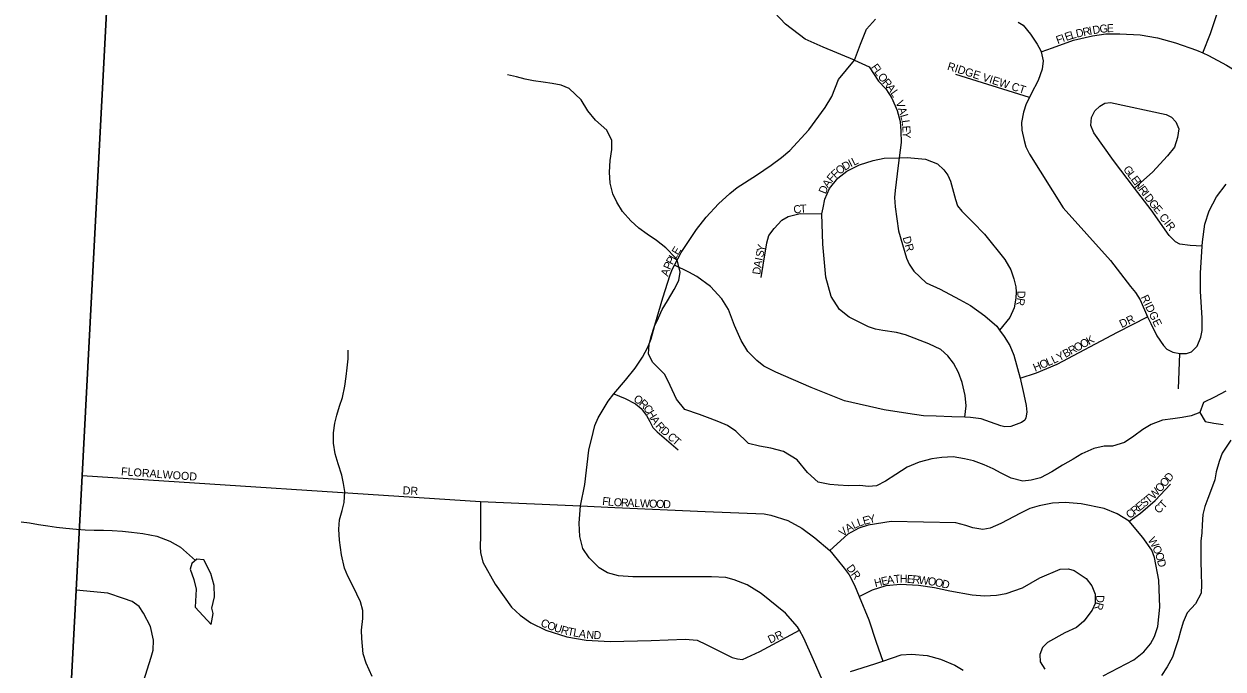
# Model space of a CAD drawing. Extents: x 1759416 to 2214760, y 252598 to 1116833.
# Drawn here: x 2005444 to 2012935, y 891835 to 895864 of the extents above; entities that cross this region are included whole.
import ezdxf

# ---------------------------------------------------------------- set-up
doc = ezdxf.new("R2010")
doc.units = 0
for name, color, linetype in [('GM_X_County_Road', 7, 'Continuous'), ('GM_X_County_Subdivision', 7, 'Continuous'), ('GM_X_County_Subdivision_Text', 7, 'Continuous'), ('GM_X_Major_Lake', 7, 'Continuous'), ('GM_X_Minor_Lake', 7, 'Continuous'), ('GM_X_Minor_River', 7, 'Continuous'), ('GM_X_Township', 7, 'Continuous'), ('GM_X_Township_Subdivision', 7, 'Continuous'), ('GM_X_Township_Subdivision_Text', 7, 'Continuous')]:
    doc.layers.add(name, color=color, linetype=linetype)

msp = doc.modelspace()

# ---------------------------------------------------------------- linework, layer by layer
at = {"layer": 'GM_X_County_Road'}
msp.add_lwpolyline([(2004887.1, 877838.9), (2004966.1, 878054.7), (2005006.3, 878210), (2005059.3, 878425.5), (2005076, 878622.8), (2005114.2, 879911.6), (2005203.2, 881311.9), (2005266.8, 882813.7), (2005306.3, 883397.6), (2005439.1, 886066.7), (2005449.8, 886268.9), (2005489.1, 887010.5), (2005555.5, 888282.1), (2005602.6, 889171.2), (2005650.9, 890084.8), (2005769.6, 892327), (2005807.5, 893043.9), (2005864.5, 894121.1), (2005998.4, 896652.4), (2006004, 896754.8), (2006008, 896849.4)], dxfattribs=at)
at = {"layer": 'GM_X_County_Subdivision'}
for points in [[(2010433.5, 891763), (2010377.4, 891893.1), (2010316.5, 892029), (2010288.5, 892077.4), (2010276.1, 892098.9), (2010201.5, 892184.6), (2010050.5, 892308), (2009962.1, 892361.6), (2009881.8, 892393.2), (2009829.7, 892406.9), (2009739.6, 892410.4), (2009247, 892411.5), (2009158.9, 892416.9), (2009088.7, 892436.6), (2009038.4, 892466.4), (2008976, 892530.1), (2008935.6, 892588), (2008917.1, 892662), (2008912.6, 892746.2), (2008921.9, 892854.4), (2008947.1, 892986.8), (2008973.8, 893201.4), (2008999.2, 893311.8), (2009010.9, 893355.9), (2009030.6, 893404.1), (2009094.1, 893508.7), (2009129.8, 893555), (2009201.4, 893639.6), (2009263, 893714.1), (2009308.6, 893782.5), (2009342.3, 893844.8), (2009362, 893897.1), (2009385.4, 893983.3), (2009434.5, 894154), (2009481.6, 894296.5), (2009495.4, 894334.7), (2009507.3, 894356.7), (2009550.8, 894437.2), (2009646.1, 894580), (2009705.7, 894658.5), (2009783.2, 894741.2), (2009854.9, 894805.7), (2009898.7, 894842), (2010020.4, 894918.9), (2010112.1, 894981.6), (2010175.9, 895030), (2010229.7, 895074.4), (2010347, 895203.4), (2010450.2, 895342.2), (2010491.9, 895410.6), (2010533.2, 895517.1), (2010633, 895637.9), (2010669.6, 895737.2), (2010708.5, 895832.2), (2010763.5, 895894.8)], [(2005807.5, 893043.9), (2008296.7, 892881.4), (2008921.9, 892854.4)]]:
    msp.add_lwpolyline(points, dxfattribs=at)
at = {"layer": 'GM_X_Major_Lake'}
for points in [[(2012952.8, 893571), (2012880.9, 893532.6), (2012812.9, 893500.3), (2012789.1, 893438.1), (2012823.4, 893382.1)], [(2012823.4, 893382.1), (2012877.5, 893370.3), (2012935.6, 893362.5)], [(2012984.1, 893264.4), (2012930.3, 893184.1), (2012910.5, 893131.9), (2012892.7, 893067.7), (2012882.9, 893017.6), (2012863, 892961.4), (2012839.2, 892901.2), (2012821.4, 892851), (2012809.6, 892800.8), (2012803.8, 892736.7), (2012802, 892686.6), (2012796.2, 892634.4), (2012796.7, 892508.2), (2012799, 892432), (2012801.2, 892361.9), (2012797.4, 892309.8), (2012763.6, 892243.5), (2012709.8, 892187.2), (2012686, 892129), (2012668.2, 892070.8), (2012654.4, 892016.7), (2012636.5, 891960.5), (2012618.7, 891910.3), (2012586.9, 891848.1), (2012551.1, 891795.8)]]:
    msp.add_lwpolyline(points, dxfattribs=at)
at = {"layer": 'GM_X_Minor_Lake'}
for points in [[(2006613.5, 892114.2), (2006627.2, 892182.4), (2006617.1, 892214.5), (2006634.9, 892286.7), (2006632.6, 892356.8), (2006612.3, 892432.9), (2006567.9, 892516.9), (2006523.8, 892520.8), (2006493.9, 892494.6), (2006482, 892458.5), (2006506.3, 892394.5), (2006520.5, 892334.4), (2006512.9, 892222.1)], [(2006512.9, 892222.1), (2006613.5, 892114.2)]]:
    msp.add_lwpolyline(points, dxfattribs=at)
at = {"layer": 'GM_X_Minor_River'}
for points in [[(2012789.2, 893437.9), (2012735.1, 893415.9), (2012679.1, 893405.7), (2012621, 893397.5), (2012557, 893389.2), (2012485, 893362.9), (2012433, 893330.7), (2012377.1, 893290.4), (2012319.2, 893250.1), (2012245.2, 893227.8), (2012193.1, 893227.7), (2012127.1, 893213.4), (2012053.1, 893179.1), (2011999.1, 893146.8), (2011931.2, 893108.5), (2011865.2, 893066.2), (2011795.3, 893029.9), (2011737.3, 893015.7), (2011683.2, 893009.4), (2011611, 893027.2), (2011548.8, 893059.1), (2011498.7, 893085), (2011442.5, 893110.9), (2011376.3, 893134.7), (2011320.2, 893148.5), (2011248, 893160.3), (2011177.9, 893156), (2011115.9, 893147.8), (2011035.8, 893127.5), (2010961.9, 893095.2), (2010889.9, 893050.8), (2010826, 893008.5), (2010770, 892980.3), (2010720, 892976.1), (2010665.9, 892981.9), (2010595.8, 892979.7), (2010529.7, 892983.5), (2010477.6, 892987.3), (2010405.4, 893003.1), (2010339.1, 893063), (2010274.7, 893142.9), (2010188.4, 893194.8), (2010110.2, 893214.5), (2010040.1, 893226.3), (2009969.9, 893244.1), (2009891.5, 893320), (2009839.3, 893355.9), (2009785.1, 893379.8), (2009731, 893399.6), (2009664.8, 893425.4), (2009572.5, 893457.2), (2009520.2, 893521.2), (2009481.8, 893605.2), (2009447.5, 893675.2), (2009371.1, 893751.1), (2009344.9, 893803.2), (2009350.7, 893861.3), (2009362.5, 893911.4), (2009384.3, 893977.7), (2009408.1, 894029.8), (2009431.9, 894080), (2009463.8, 894134.2), (2009505.6, 894206.5), (2009535.4, 894262.8), (2009543.2, 894314.9), (2009526.9, 894383), (2009514.8, 894403), (2009454.5, 894466.9), (2009396.2, 894510.8), (2009338, 894550.7), (2009285.8, 894588.6), (2009235.5, 894634.5), (2009183.3, 894692.5), (2009147, 894750.5), (2009122.7, 894802.5), (2009106.5, 894870.6), (2009102.2, 894938.7), (2009105.9, 895010.9), (2009115.7, 895081.1), (2009117.5, 895137.2), (2009085.2, 895201.2), (2009014.8, 895263.1), (2008966.5, 895321), (2008924.2, 895391), (2008849.8, 895460.9), (2008799.7, 895482.8), (2008743.6, 895492.6), (2008687.5, 895500.5), (2008627.4, 895508.3), (2008575.2, 895520.1), (2008521.1, 895534), (2008465, 895545.8)], [(2007620.1, 891789), (2007581.8, 891871.1), (2007563.5, 891931.1), (2007555.1, 892025.3), (2007553, 892077.4), (2007560.7, 892151.6), (2007560.5, 892201.7), (2007546.3, 892255.7), (2007501.8, 892349.8), (2007467.5, 892415.8), (2007447.3, 892465.8), (2007427, 892547.9), (2007414.6, 892640.1), (2007410.3, 892708.2), (2007416.1, 892766.4), (2007431.9, 892824.5), (2007443.8, 892874.7), (2007449.5, 892944.9), (2007441.3, 892994.9), (2007429.1, 893047), (2007406.8, 893117.1), (2007388.5, 893179.2), (2007378.2, 893245.2), (2007378, 893311.4), (2007385.8, 893371.5), (2007399.6, 893421.7), (2007415.4, 893477.9), (2007433.2, 893532), (2007449, 893602.2), (2007456.8, 893662.4), (2007462.6, 893716.5), (2007470.4, 893772.7), (2007470.1, 893826.8)], [(2005427.4, 892755.5), (2005479.5, 892747.7), (2005535.6, 892737.9), (2005593.7, 892730), (2005647.8, 892722.2), (2005705.9, 892714.4), (2005772, 892708.6), (2005826.1, 892704.8), (2005882.2, 892703), (2005940.3, 892703.2), (2005994.4, 892701.4), (2006060.5, 892695.6), (2006116.6, 892689.8), (2006186.7, 892682), (2006274.9, 892664.2), (2006355.1, 892634.5), (2006421.4, 892596.6), (2006516.2, 892514.1)]]:
    msp.add_lwpolyline(points, dxfattribs=at)
at = {"layer": 'GM_X_Township'}
for points in [[(1998107.8, 897126.5), (1999328.7, 897063.4), (2003204.9, 896913.2), (2006004, 896754.8), (2005998.4, 896652.4), (2005864.5, 894121.1), (2005807.5, 893043.9), (2005769.6, 892327), (2005650.9, 890084.8), (2005602.6, 889171.2), (2005555.5, 888282.1), (2005489.1, 887010.5), (2005449.8, 886268.9), (2005439.1, 886066.7), (2005306.3, 883397.6)], [(2005306.3, 883397.6), (2005439.1, 886066.7), (2005449.8, 886268.9), (2005489.1, 887010.5), (2005555.5, 888282.1), (2005602.6, 889171.2), (2005650.9, 890084.8), (2005769.6, 892327), (2005807.5, 893043.9), (2005864.5, 894121.1), (2005998.4, 896652.4), (2010326.5, 896491.5), (2011122.5, 896461.9), (2011648.1, 896428), (2012134.2, 896416.9), (2013353.6, 896345), (2014249.7, 896310.5), (2015226.5, 896288.6), (2016682.3, 896255.5), (2022025.3, 896071.6)]]:
    msp.add_lwpolyline(points, dxfattribs=at)
at = {"layer": 'GM_X_Township_Subdivision'}
for points in [[(2010633, 895637.9), (2010436.5, 895719.9), (2010324.3, 895769.6), (2010201.2, 895862.4), (2010132.2, 895935.8), (2010106.2, 895980), (2010077.1, 896045.8), (2010060.9, 896112.8), (2010072.8, 896195.9), (2010113.8, 896269.3), (2010166.7, 896338.3), (2010254.1, 896423.6), (2010326.5, 896491.4), (2010327.6, 896492.2)], [(2012808.9, 895683), (2012857, 895804), (2012910.4, 895967.9), (2012927, 896039.9), (2012925.4, 896084), (2012911.8, 896132.2), (2012892, 896158.4), (2012864.2, 896182.7), (2012808.3, 896211.2), (2012358, 896362.9), (2012202.7, 896393.3), (2012064.3, 896398.1), (2011937.6, 896386.4), (2011858, 896369.6), (2011775.6, 896366.1), (2011716.3, 896383.7), (2011698.1, 896395.6)], [(2011654.5, 895876.2), (2011686.4, 895855.9), (2011732, 895801.4), (2011773.5, 895737), (2011795.2, 895700.7), (2011797.9, 895690.3), (2011803, 895670.6), (2011810.7, 895634.5), (2011804.2, 895582.4), (2011779.6, 895510.5), (2011736.9, 895428.7), (2011725.1, 895405.6), (2011704.4, 895364.8), (2011687.9, 895312.9), (2011675.4, 895248.9), (2011677, 895200.8), (2011692.5, 895136.5), (2011702.2, 895096.4), (2011725.8, 895050.1), (2011935.2, 894715.7), (2012232.8, 894386.6), (2012357.6, 894225.3), (2012387.3, 894187), (2012417, 894140.6), (2012462.1, 894034), (2012483.8, 893993.8), (2012521.2, 893917.3), (2012562.8, 893856.9), (2012584.6, 893832.6), (2012620.5, 893814.3), (2012664.4, 893805.9), (2012706.5, 893805.6), (2012738.6, 893817.3), (2012772.9, 893851.1), (2012795.4, 893907), (2012803.7, 893949), (2012804.4, 894027.1), (2012793.8, 894195.6), (2012794.7, 894307.8), (2012804.6, 894475.7), (2012806.3, 894504), (2012821.2, 894614.1), (2012847.9, 894698), (2012894.7, 894783.8), (2012955.4, 894863.5)], [(2011797.9, 895690.3), (2011869.4, 895716.1), (2011999.9, 895763.1), (2012120.2, 895790.2), (2012202.4, 895803.5), (2012290.5, 895802.8), (2012416.6, 895795.7), (2012526.5, 895776.8), (2012638.4, 895745.7), (2012768.1, 895700.6), (2012808.9, 895683), (2012843.9, 895667.9), (2012955.5, 895606.8), (2013069, 895537.7), (2013132.8, 895499.1), (2013214.6, 895466.4), (2013314.4, 895437.5)], [(2010633, 895637.9), (2010723.6, 895596.9), (2010782.7, 895506.8), (2010828.3, 895458.4), (2010865.9, 895399.9), (2010899.3, 895323.5), (2010918.7, 895255.2), (2010922.3, 895195.1), (2010923.7, 895122.9), (2010910.9, 895028.8), (2010904.5, 894980.9), (2010887.2, 894824.7), (2010882.8, 894780.7), (2010886.3, 894722.5), (2010907.1, 894572.1), (2010957.8, 894401.3), (2010973.5, 894363.1), (2011003.2, 894320.8), (2011080.6, 894248), (2011168.4, 894207.2), (2011288, 894144.1), (2011357.7, 894105.4), (2011447.3, 894040.6), (2011520.8, 893975.8), (2011539.1, 893951), (2011568.3, 893911.3), (2011603.9, 893856.9), (2011627.4, 893794.6), (2011668.3, 893652), (2011691.4, 893549.6), (2011704.9, 893481.3), (2011708.5, 893439.3), (2011702.3, 893405.2), (2011696.1, 893389.3), (2011676, 893375.4), (2011609.9, 893350.9), (2011571.7, 893348.2), (2011547.7, 893354.4), (2011481.8, 893377), (2011424, 893397.6), (2011358, 893406.1), (2011321.7, 893407.7), (2011239.9, 893411.1), (2011143.8, 893413.9), (2011063.8, 893416.6), (2010965.8, 893431.4), (2010817.9, 893454.7), (2010570.1, 893510.9), (2010362.6, 893592.8), (2010141.2, 893688.8), (2010065.4, 893727.5), (2010021.6, 893762), (2009966.1, 893818.6), (2009924.6, 893887), (2009883.3, 893981.5), (2009846.1, 894080), (2009804.6, 894146.5), (2009733.2, 894225.2), (2009647.6, 894286.1), (2009597.8, 894314.5), (2009507.3, 894356.7)], [(2011725.1, 895405.6), (2011265.5, 895548.9)], [(2012804.6, 894475.7), (2012730.1, 894480.6), (2012664.1, 894489.2), (2012638.2, 894503.4), (2012598.4, 894543.8), (2012486.8, 894703.1), (2012382.7, 894838.2), (2012250, 895011.6), (2012127.3, 895185), (2012109.6, 895229.2), (2012114.1, 895279.3), (2012134.4, 895321.2), (2012164.7, 895351), (2012196.9, 895368.7), (2012230.9, 895374.5), (2012580.6, 895299.4), (2012612.5, 895281.1), (2012640.3, 895252.8), (2012657.9, 895208.6), (2012649.5, 895154.6), (2012631, 895094.6), (2012588.5, 895040.9), (2012493.6, 894939.5), (2012384.7, 894840.2)], [(2011321.7, 893407.7), (2011330.5, 893478.5), (2011323.1, 893544.7), (2011305.7, 893625), (2011282.2, 893687.3), (2011250.7, 893745.7), (2011215, 893792), (2011171.3, 893830.5), (2011097.5, 893867.2), (2010951.9, 893922.5), (2010895.9, 893937), (2010809.9, 893949.7), (2010764, 893958.1), (2010720, 893972.5), (2010598.4, 894033.6), (2010538.8, 894080.2), (2010487.4, 894162.8), (2010454.3, 894283.3), (2010434, 894489.9), (2010429.6, 894678.3), (2010435.9, 894716.3), (2010448.3, 894770.3), (2010476.9, 894836.2), (2010527.5, 894901.9), (2010583.9, 894945.5), (2010664.3, 894984.9), (2010748.6, 895012.2), (2010818.8, 895025.6), (2010910.9, 895028.8), (2010960.9, 895030.5), (2011076.9, 895019.5), (2011150.8, 894990.8), (2011190.5, 894952.4), (2011216.3, 894920.1), (2011232, 894881.9), (2011263.1, 894767.4), (2011276.8, 894729.2), (2011302.5, 894695), (2011372, 894626.3), (2011445.5, 894551.5), (2011572.3, 894392.2), (2011609.8, 894327.7), (2011627.3, 894271.5), (2011640.9, 894223.3), (2011642.7, 894191.2), (2011640.3, 894151.2), (2011629.8, 894091.1), (2011603.3, 894031.2), (2011539.1, 893951)], [(2010049.9, 894280.7), (2010062.6, 894356.7), (2010085.7, 894496.8), (2010098.1, 894542.8), (2010130.5, 894586.6), (2010179, 894638.3), (2010219.2, 894662), (2010293.4, 894679.4), (2010429.6, 894678.3)], [(2011668.3, 893652), (2011770.6, 893685.2), (2011899.2, 893740.2), (2012275.2, 893939.4), (2012462.1, 894034)], [(2012656.1, 893586.2), (2012664.4, 893805.9)], [(2009129.8, 893555), (2009200.1, 893525.4), (2009264.4, 893491.7), (2009300.6, 893461.8), (2009332.9, 893417.9), (2009353.1, 893382), (2009373.4, 893344), (2009399.6, 893316.1), (2009530.4, 893204.7)], [(2012347.6, 892758.6), (2012420, 892808.1), (2012510.8, 892887.5), (2012605.7, 892988.9)], [(2008296.7, 892881.4), (2008296.4, 892666.4), (2008294.8, 892598.2), (2008297, 892562.2), (2008311.4, 892502.2), (2008388.4, 892364.4), (2008489.4, 892222.7), (2008543.7, 892170.9), (2008610.1, 892123.2), (2008704.5, 892077.6), (2008834.9, 892036.3), (2008957.1, 892015), (2009107.3, 892007.9), (2009361.6, 892013.3), (2009575.8, 892022.6), (2009649.9, 892015), (2009706.1, 891989.3), (2009868.8, 891908.1), (2009900.9, 891898.3), (2009933, 891894.5), (2010040.8, 891945.2), (2010288.5, 892077.4)], [(2008921.9, 892854.4), (2009135.3, 892843.7), (2009699.6, 892818.9), (2010067.8, 892803.8), (2010109.8, 892795.4), (2010215.6, 892762.5), (2010303.3, 892715.7), (2010384.9, 892654.9), (2010478.3, 892575.9), (2010523.9, 892519.4), (2010567.5, 892465), (2010599.2, 892422.7), (2010632.7, 892358.3), (2010661.6, 892289.3), (2010723, 892143.1), (2010767.9, 892002.4), (2010809.3, 891885.1)], [(2012185.5, 891792.2), (2012378.5, 891892.8), (2012440.9, 891942.3), (2012481.4, 891992.1), (2012505.8, 892037.9), (2012528.3, 892099.9), (2012539.3, 892222), (2012534.7, 892390.4), (2012505.9, 892532.9), (2012490.2, 892577.1), (2012434.8, 892657.7), (2012347.6, 892758.6), (2012273.9, 892805.3), (2012192.1, 892838.1), (2012048.2, 892867.3), (2011948.1, 892876.2), (2011870, 892870.8), (2011785.8, 892855.5), (2011727.6, 892838), (2011669.3, 892808.4), (2011546.7, 892743.3), (2011480.4, 892715.8), (2011434.3, 892706.2), (2011372.3, 892716.7), (2011328.4, 892731.1), (2011266.5, 892747.7), (2010862.2, 892757.1), (2010717.9, 892734.2), (2010659.6, 892714.7), (2010591.3, 892677.2), (2010478.3, 892575.9)], [(2010661.6, 892289.3), (2010744.6, 892329.3), (2010830.9, 892356.6), (2010919, 892365.9), (2011033.1, 892358.9), (2011133.1, 892344), (2011228.9, 892323.2), (2011366.9, 892298), (2011444.9, 892293.3), (2011519, 892296.7), (2011579.1, 892306.2), (2011681.5, 892341.4), (2011790.1, 892404.6), (2011916.7, 892459.7), (2011968.8, 892461.2), (2012004.7, 892450.9), (2012080.4, 892400.2), (2012116, 892355.8), (2012135.6, 892303.6), (2012135.1, 892245.5), (2012116.8, 892203.5), (2012066.2, 892133.8), (2012019.8, 892094.1), (2011947.5, 892060.7), (2011838.9, 892001.5), (2011806.6, 891969.7), (2011790.2, 891925.7), (2011791.8, 891879.6), (2011821.5, 891835.3)], [(2006192, 891758), (2006238.8, 891908.8), (2006250.5, 891953), (2006254.2, 892015.1), (2006235.6, 892101.2), (2006191.1, 892185.1), (2006164.8, 892225), (2006120.6, 892256.8), (2006066.4, 892276.5), (2005967.8, 892308.7), (2005769.6, 892327)], [(2010608.2, 891819.4), (2010758.8, 891868.3), (2010809.3, 891885.1), (2010923.4, 891923), (2010989.5, 891928.5), (2011087.5, 891919.6), (2011169.4, 891896.9), (2011259.2, 891860.1), (2011310.9, 891827.6)]]:
    msp.add_lwpolyline(points, dxfattribs=at)

# ---------------------------------------------------------------- texts
at = {"layer": 'GM_X_County_Subdivision_Text'}
for s, rotation, p in [('L', 60.10938, (2009512.6, 894386.4)), ('E', 58.59115, (2009530, 894416.7)), ('P', 65.34125, (2009481.2, 894324.8)), ('P', 60.70921, (2009495.4, 894355.9)), ('A', 70.91524, (2009467.3, 894284.4)), ('FLORALWOOD', 355.82945, (2006049.4, 893045.8)), ('DR', 356.98902, (2007809.2, 892927))]:
    msp.add_text(s, height=50, rotation=rotation, dxfattribs=at).set_placement(p)
at = {"layer": 'GM_X_Township_Subdivision_Text'}
for s, rotation, p in [('R', 12.45769, (2012064.1, 895787.8)), ('I', 10.86406, (2012102.4, 895796.3)), ('D', 9.32939, (2012123.6, 895800.4)), ('G', 6.85666, (2012166.5, 895807.4)), ('E', 1.28395, (2012208.9, 895812.6)), ('F', 19.87806, (2011901.9, 895738)), ('I', 19.90964, (2011935, 895750)), ('E', 19.47186, (2011955.6, 895757.5)), ('L', 15.51387, (2011987.9, 895768.9)), ('D', 12.66866, (2012021.2, 895778.2)), ('F', 305.5091, (2010733.4, 895593.9)), ('RIDGE VIEW CT', 342.44797, (2011208.3, 895579.8)), ('L', 304.76599, (2010753.7, 895565.4)), ('O', 306.81774, (2010774.9, 895534.9)), ('R', 310.63071, (2010803.6, 895496.9)), ('A', 306.54642, (2010828.8, 895467.5)), ('L', 304.74355, (2010854.7, 895432.5)), ('V', 289.72733, (2010888.7, 895376.1)), ('A', 288.06861, (2010903.5, 895335)), ('L', 285.71275, (2010917, 895293.7)), ('L', 278.02967, (2010926.1, 895261.5)), ('E', 273.30712, (2010930.9, 895227.8)), ('Y', 270.48093, (2010932.9, 895193.3)), ('I', 26.56505, (2010609.2, 894968.5)), ('L', 25.86859, (2010628.7, 894978.2)), ('F', 43.22216, (2010513.7, 894897.7)), ('O', 37.20211, (2010538.3, 894920.9)), ('D', 30.37912, (2010572, 894946.6)), ('G', 306.87427, (2012308.6, 894956.1)), ('L', 306.89238, (2012335, 894920.9)), ('A', 55.11543, (2010467.5, 894836.9)), ('F', 49.56467, (2010491.9, 894872)), ('E', 306.85897, (2012356.2, 894892.7)), ('N', 306.89862, (2012377.3, 894864.5)), ('D', 68.39748, (2010452.7, 894798.7)), ('R', 306.88448, (2012403.7, 894829.3)), ('I', 306.90054, (2012427.5, 894797.6)), ('D', 306.89175, (2012440.7, 894780)), ('C', 11.49091, (2010256.6, 894677.8)), ('T', 2.1858, (2010293.3, 894685.4)), ('G', 307.61938, (2012467.5, 894744.3)), ('E', 310.48254, (2012496.1, 894707.3)), ('CIR', 307.87835, (2012532.9, 894657)), ('DR', 285.52913, (2010933, 894530.5)), ('S', 77.89188, (2010062, 894403.6)), ('Y', 77.91354, (2010069.4, 894438)), ('D', 81.75242, (2010043.4, 894296.1)), ('A', 79.65019, (2010049.6, 894339.2)), ('I', 78.06404, (2010057.5, 894382.1)), ('R', 260.70538, (2011649.5, 894156.1)), ('D', 268.51382, (2011650.5, 894198.3)), ('RIDGE', 295.60065, (2012419.6, 894158)), ('DR', 25.20731, (2012301.5, 893964.5)), ('O', 28.55104, (2012058, 893836.7)), ('K', 28.54941, (2012096.7, 893857.7)), ('Y', 28.28849, (2011910.8, 893756.8)), ('B', 28.54088, (2011949.8, 893777.8)), ('R', 28.55687, (2011984.6, 893796.7)), ('O', 28.53021, (2012019.4, 893815.7)), ('H', 22.79973, (2011760.7, 893691.9)), ('O', 22.80336, (2011801.3, 893709)), ('L', 22.81112, (2011841.8, 893726)), ('L', 25.12812, (2011876.3, 893740.6)), ('O', 326.52813, (2009247.5, 893511.2)), ('R', 318.16079, (2009282.6, 893488.1)), ('C', 306.15593, (2009310.3, 893463.7)), ('H', 302.41085, (2009333.2, 893432.5)), ('A', 302.33206, (2009356.7, 893395.3)), ('R', 311.99581, (2009385.8, 893350.8)), ('D', 318.95661, (2009417.1, 893316.8)), ('C', 318.81408, (2009460.2, 893279.2)), ('T', 318.80894, (2009490, 893253.1)), ('O', 48.60491, (2012542.3, 892935)), ('O', 48.55705, (2012571.4, 892968)), ('D', 48.58905, (2012600.5, 893001)), ('T', 39.45818, (2012469.6, 892865)), ('W', 46.67162, (2012501.8, 892892.1)), ('F', 353.75936, (2009055, 892861)), ('L', 354.10924, (2009090.3, 892857.1)), ('O', 356.76148, (2009127.8, 892853.3)), ('R', 357.83106, (2009172.8, 892850.8)), ('A', 357.85355, (2009212.4, 892849.3)), ('L', 357.8415, (2009256.3, 892847.6)), ('W', 357.84716, (2009291.5, 892846.3)), ('O', 357.86488, (2009348.7, 892844.1)), ('O', 357.85787, (2009392.7, 892842.5)), ('D', 357.85355, (2009436.6, 892840.8)), ('R', 38.73749, (2012383.3, 892795.7)), ('E', 38.73944, (2012414.2, 892820.5)), ('S', 38.75682, (2012441.7, 892842.5)), ('C', 41.80493, (2012531.6, 892802.4)), ('T', 47.24627, (2012564.8, 892832.5)), ('L', 18.97929, (2010659, 892723.4)), ('E', 15.37493, (2010691.4, 892734.6)), ('Y', 12.98642, (2010724.9, 892743.8)), ('C', 38.73567, (2012352.4, 892771)), ('V', 39.86154, (2010560, 892659.5)), ('A', 30.53646, (2010592, 892686.4)), ('L', 26.56505, (2010629.1, 892708.3)), ('W', 300.9753, (2012463, 892641.1)), ('O', 294.93239, (2012491.8, 892593.2)), ('O', 286.81023, (2012509.7, 892555.1)), ('DR', 306.24631, (2010579.3, 892465.8)), ('D', 283.63344, (2012522.2, 892513.7)), ('H', 14.76247, (2010763.1, 892345.9)), ('E', 12.64439, (2010805.1, 892357)), ('A', 9.04193, (2010838.7, 892364.5)), ('T', 6.40657, (2010881.5, 892371.4)), ('H', 358.44771, (2010914.6, 892375.2)), ('E', 355.5971, (2010958, 892374)), ('R', 355.16174, (2010993, 892371.4)), ('W', 353.03972, (2011031.9, 892368.1)), ('O', 351.84208, (2011088.4, 892361.2)), ('O', 348.02128, (2011131.1, 892355.1)), ('D', 347.30522, (2011174, 892346)), ('R', 255.79293, (2012142.3, 892256.5)), ('D', 268.20735, (2012143.3, 892297.6)), ('C', 334.54292, (2008666.7, 892107.5)), ('O', 340.69548, (2008707.9, 892088.3)), ('U', 342.91151, (2008751.4, 892073.1)), ('R', 343.73054, (2008794.3, 892059.9)), ('T', 348.30569, (2008836.5, 892047.8)), ('L', 349.91489, (2008872.5, 892040.4)), ('A', 350.70651, (2008907.9, 892034.1)), ('N', 356.16483, (2008956.5, 892026.4)), ('D', 357.80852, (2009002, 892023.3)), ('DR', 25.20174, (2010105.9, 891993.3))]:
    msp.add_text(s, height=50, rotation=rotation, dxfattribs=at).set_placement(p)

doc.saveas('drawing.dxf')
